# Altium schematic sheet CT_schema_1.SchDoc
size 586 x 258 mm
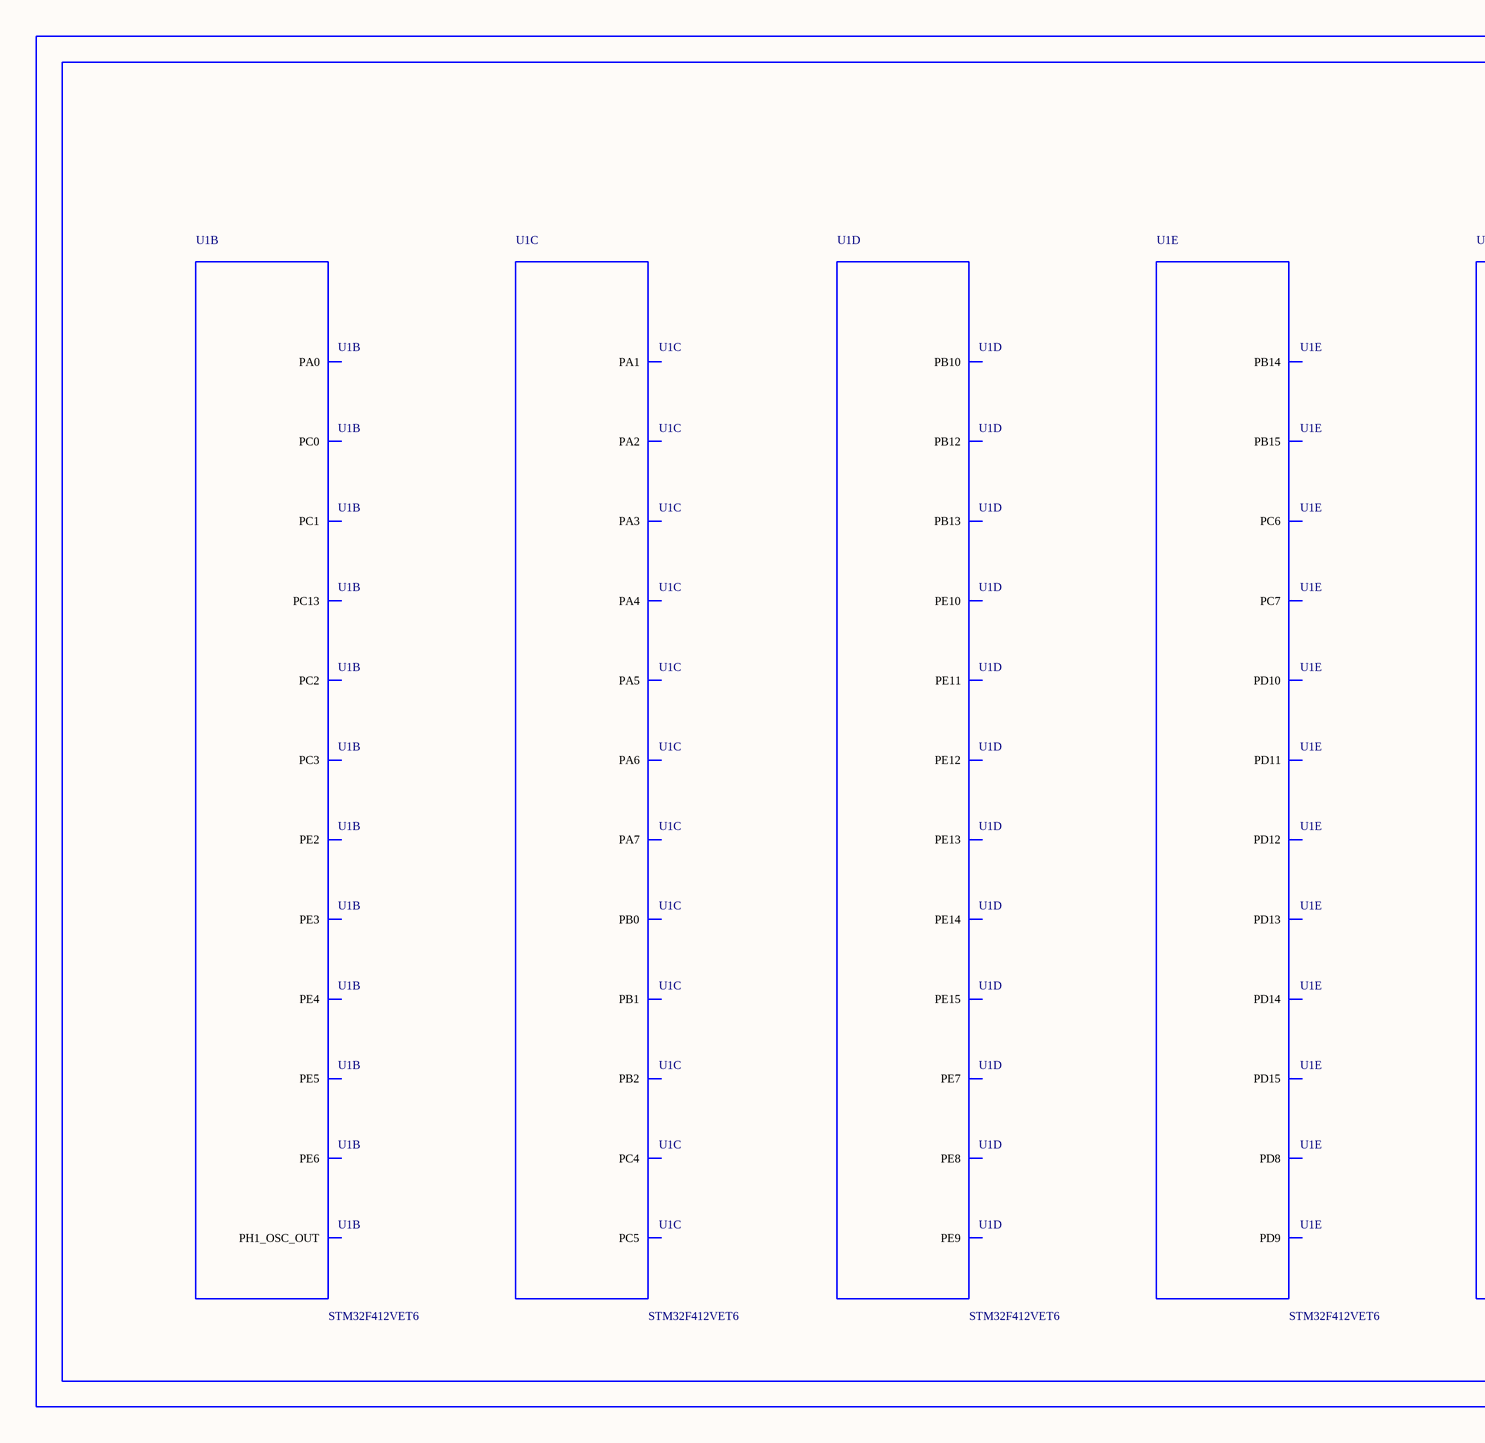
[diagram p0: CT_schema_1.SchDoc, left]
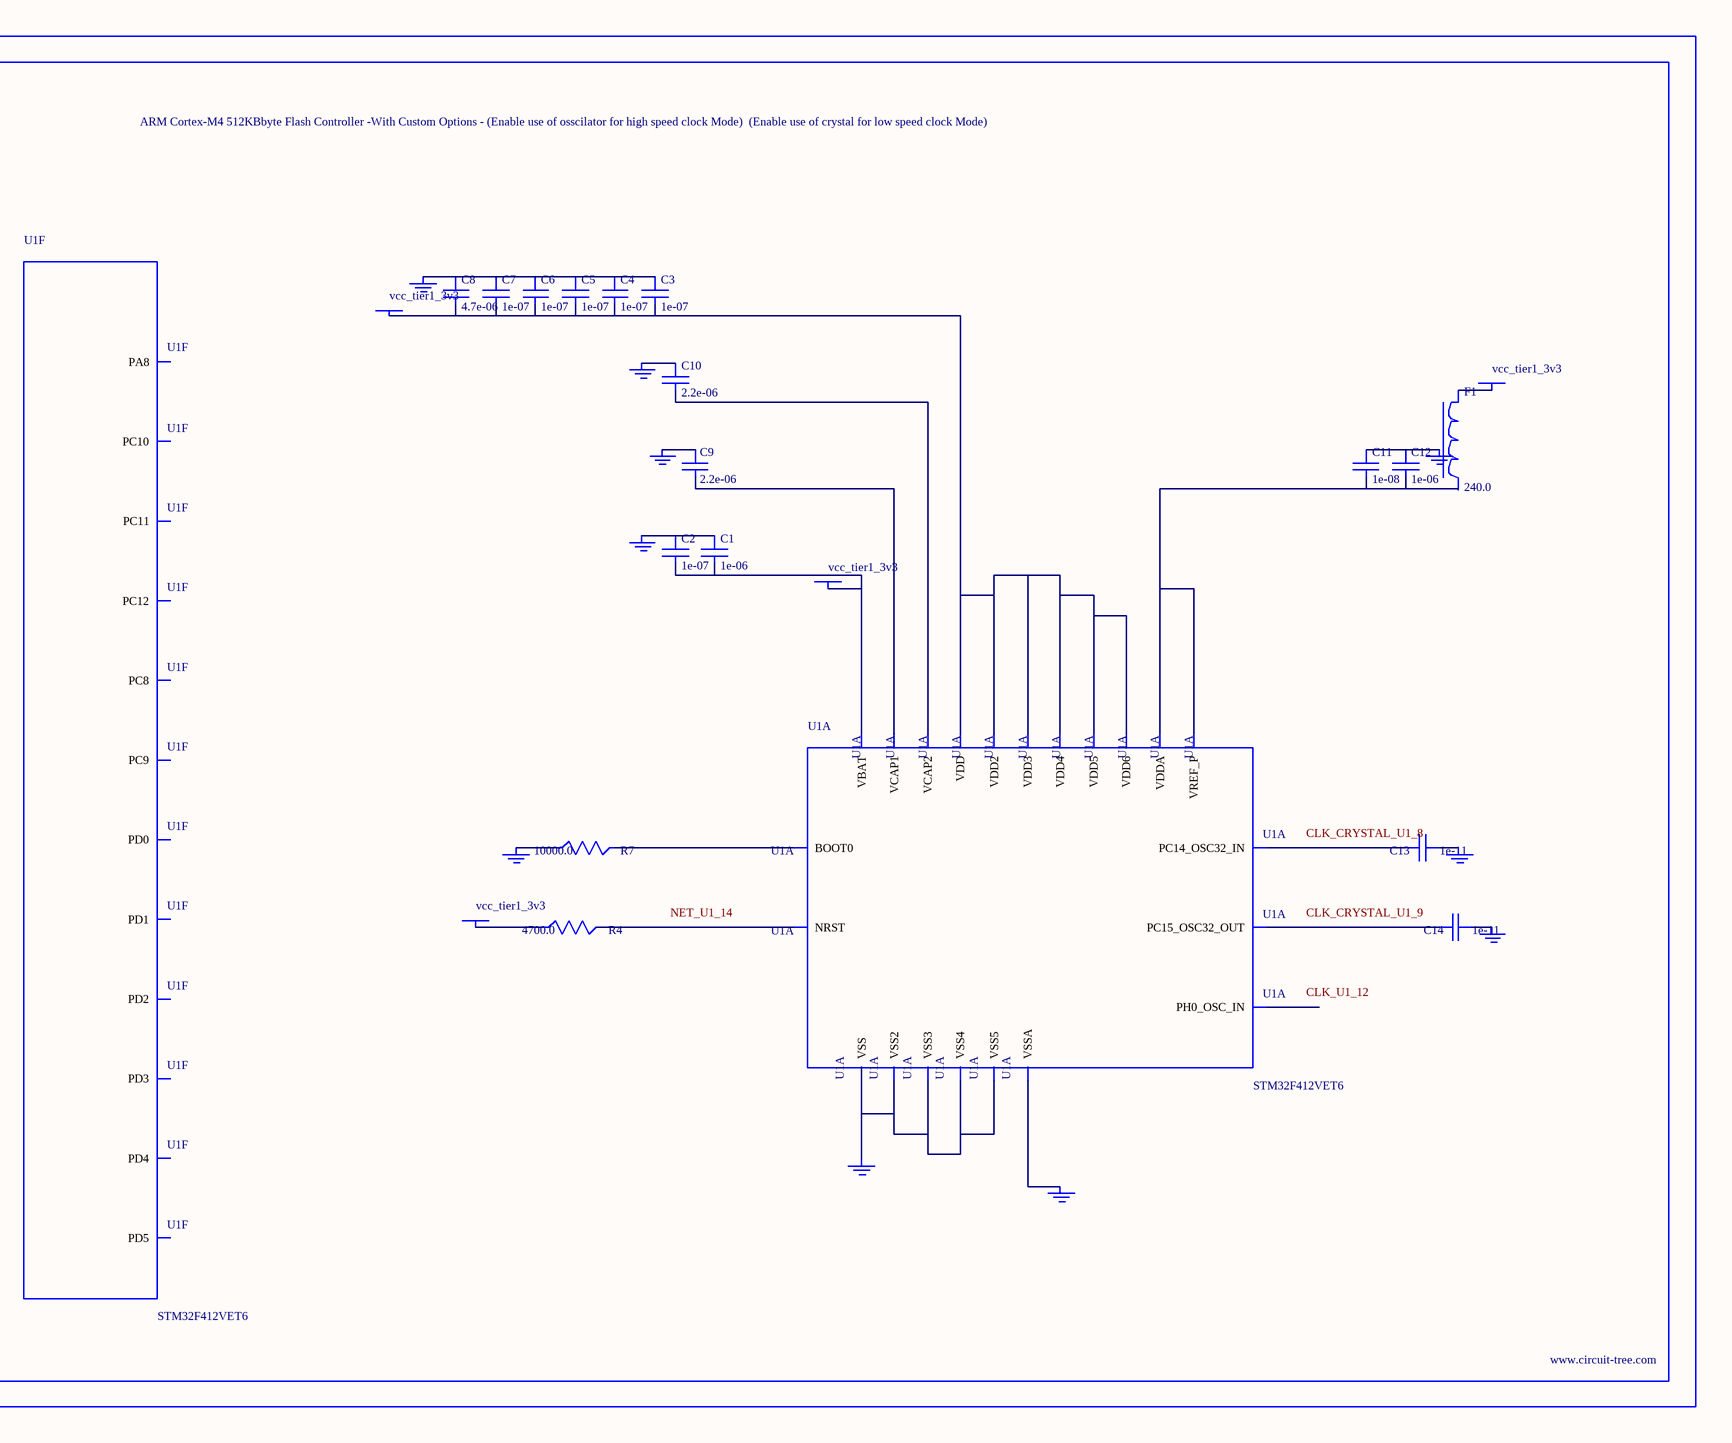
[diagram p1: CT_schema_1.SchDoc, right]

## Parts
BORDER0  (no value)
C1  1e-06  [C0603]
C2  1e-07  [C0603]
C3  1e-07  [C0603]
C4  1e-07  [C0603]
C5  1e-07  [C0603]
C6  1e-07  [C0603]
C7  1e-07  [C0603]
C8  4.7e-06  [C0603]
C9  2.2e-06  [C0603]
C10  2.2e-06  [C0603]
C11  1e-08  [C0603]
C12  1e-06  [C0603]
C13  1e-11  [C0402]
C14  1e-11  [C0402]
F1  240.0  [L0603]
GND_INSTANCE_0_0  (no value)
GND_INSTANCE_0_1  (no value)
GND_INSTANCE_0_2  (no value)
GND_INSTANCE_0_3  (no value)
GND_INSTANCE_0_4  (no value)
GND_INSTANCE_0_5  (no value)
GND_INSTANCE_0_6  (no value)
GND_INSTANCE_0_7  (no value)
GND_INSTANCE_0_8  (no value)
GND_INSTANCE_0_9  (no value)
POWER_INSTANCE_0_0  vcc_tier1_3v3
POWER_INSTANCE_0_1  vcc_tier1_3v3
POWER_INSTANCE_0_2  vcc_tier1_3v3
POWER_INSTANCE_0_3  vcc_tier1_3v3
R4  4700.0  [R0603]
R7  10000.0  [R0603]
U1  STM32F412VET6  [LQFP100]  (parts A,B,C,D,E,F of 9)

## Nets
NetC1_1: C1.1 C2.1 GND_INSTANCE_0_0.0(GND)
NetC1_2: C1.2 C2.2 POWER_INSTANCE_0_0.0(PWR) U1.6(VBAT)
NetC3_1: C3.1 C4.1 C5.1 C6.1 C7.1 C8.1 GND_INSTANCE_0_3.0(GND)
NetC3_2: C3.2 C4.2 C5.2 C6.2 C7.2 C8.2 POWER_INSTANCE_0_1.0(PWR) U1.11(VDD) U1.19(VDD2) U1.28(VDD3) U1.50(VDD4) U1.75(VDD5) U1.100(VDD6)
NetC9_1: C9.1 GND_INSTANCE_0_6.0(GND)
NetC9_2: C9.2 U1.48(VCAP1)
NetC10_1: C10.1 GND_INSTANCE_0_7.0(GND)
NetC10_2: C10.2 U1.73(VCAP2)
NetC11_1: C11.1 C12.1 GND_INSTANCE_0_5.0(GND)
NetC11_2: C11.2 C12.2 U1.21(VREF_P) U1.22(VDDA)
NetC13_1: C13.1 GND_INSTANCE_0_1.0(GND)
NetC13_2: C13.2 U1.8(PC14_OSC32_IN)
NetC14_1: C14.1 GND_INSTANCE_0_2.0(GND)
NetC14_2: C14.2 U1.9(PC15_OSC32_OUT)
NetF1_1: F1.1 POWER_INSTANCE_0_2.0(PWR)
NetGND_INSTANCE_0_4_0: GND_INSTANCE_0_4.0(GND) U1.20(VSSA)
NetGND_INSTANCE_0_8_0: GND_INSTANCE_0_8.0(GND) R7.1
NetGND_INSTANCE_0_9_0: GND_INSTANCE_0_9.0(GND) U1.10(VSS) U1.27(VSS2) U1.49(VSS3) U1.74(VSS4) U1.99(VSS5)
NetPOWER_INSTANCE_0_3_0: POWER_INSTANCE_0_3.0(PWR) R4.1
NetR4_2: R4.2 U1.14(NRST)
NetR7_2: R7.2 U1.94(BOOT0)

Not connected (* = marked no-connect by the designer): F1 2; U1 1(PE2) 2(PE3) 3(PE4) 4(PE5) 5(PE6) 7(PC13) 12(PH0_OSC_IN) 13(PH1_OSC_OUT) 15(PC0) 16(PC1) 17(PC2) 18(PC3) 23(PA0) 24(PA1) 25(PA2) 26(PA3) 29(PA4) 30(PA5) 31(PA6) 32(PA7) 33(PC4) 34(PC5) 35(PB0) 36(PB1) 37(PB2) 38(PE7) 39(PE8) 40(PE9) 41(PE10) 42(PE11) 43(PE12) 44(PE13) 45(PE14) 46(PE15) 47(PB10) 51(PB12) 52(PB13) 53(PB14) 54(PB15) 55(PD8) 56(PD9) 57(PD10) 58(PD11) 59(PD12) 60(PD13) 61(PD14) 62(PD15) 63(PC6) 64(PC7) 65(PC8) 66(PC9) 67(PA8) 78(PC10) 79(PC11) 80(PC12) 81(PD0) 82(PD1) 83(PD2) 84(PD3) 85(PD4) 86(PD5)

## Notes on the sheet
- Labels drawn without touching a wire or pin: CLK_CRYSTAL_U1_8, CLK_CRYSTAL_U1_9, CLK_U1_12, NET_U1_14

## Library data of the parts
BORDER0 = BORDER_PAGE0
C1 C12 = C0603C105K3RACTU
C2-C7 = 06035C104K4Z2A
C8 = GRM188R6YA475KE15D
C9 C10 = C0603C225K8RACTU
C11 = 06035C103K4Z2A
C13 C14 = C0402C100K3GACTU
F1 = Z0603C241ASMST
GND_INSTANCE_0_0-GND_INSTANCE_0_9 = GND
POWER_INSTANCE_0_0-POWER_INSTANCE_0_3 = PWR
R4 = RC0603JR-074K7L
R7 = RC0603JR-0710KL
